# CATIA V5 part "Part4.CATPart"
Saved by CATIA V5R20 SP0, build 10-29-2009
Part number: Part4
Bounding box of the stored display mesh (mm): x -5 to 5, y -6.744 to 7.401, z 48.505 to 78.505
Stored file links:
  C:\Documents and Settings\Media\Escritorio\GATO_ALAMBRICO\Part4.CATPart
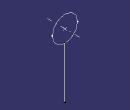
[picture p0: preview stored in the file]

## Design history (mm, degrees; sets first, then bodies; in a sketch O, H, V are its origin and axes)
Set1
  Line1: type PtDir, RefPoint DatumPoint1, Direction xy-plane, Start 0, End 20
  DatumPoint1
  Point1: type OnCurve, Support Line1, Length 5, RefPoint vertex of Line1
  Circle1: type CtrRad, Start 0, End 180, Radius 5, Center Point1, Support zx-plane, FirstDirection (0, 1, 0)
  Line2: stored without definition
  AxisLine1: Element Circle1
Body1 (main body)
